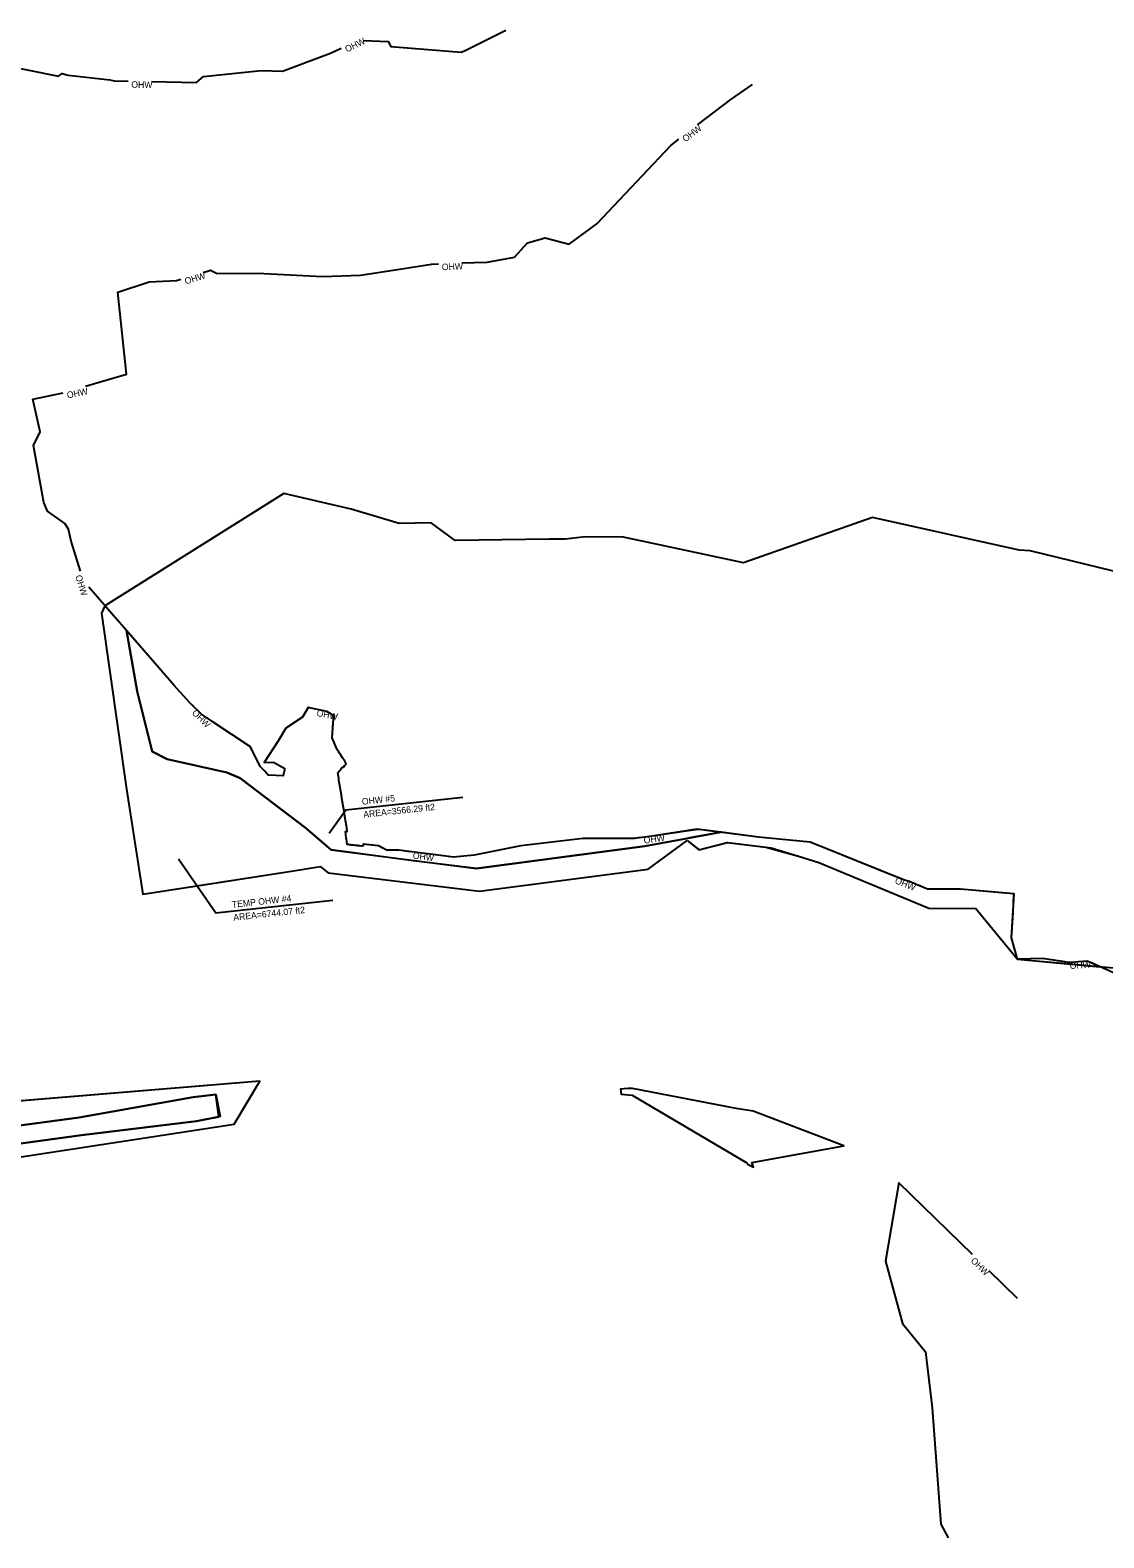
# Model space of a CAD drawing. Extents: x 1509537 to 1510685, y 401169 to 402194.
# Drawn here: x 1509933 to 1510396, y 401323 to 401974 of the extents above; entities that cross this region are included whole.
import ezdxf

# ---------------------------------------------------------------- set-up
doc = ezdxf.new("R2010")
doc.units = 0
for name, color, linetype in [('LAWE', 7, 'Continuous'), ('LAWE_P', 7, 'Continuous'), ('LAWE_P_T', 7, 'Continuous'), ('Level 6', 7, 'Continuous'), ('Level 9', 7, 'Continuous')]:
    doc.layers.add(name, color=color, linetype=linetype)

msp = doc.modelspace()

# ---------------------------------------------------------------- linework, layer by layer
at = {"layer": 'LAWE'}
for points in [[(1510076.76, 401969.93), (1510087.46, 401969.45), (1510088.64, 401967.38), (1510118.91, 401964.87), (1510120.62, 401965.57), (1510138.21, 401974.37)], [(1509902.92, 401964.05), (1509908.24, 401960.7), (1509910.79, 401962.61), (1509914.24, 401961.76), (1509918.65, 401959.85), (1509945.07, 401954.56), (1509946.65, 401955.7), (1509949.25, 401954.95), (1509967.25, 401952.86), (1509969.07, 401952.46), (1509975.16, 401952.34)], [(1509985.27, 401952.15), (1510004.66, 401951.79), (1510007.69, 401954.34), (1510032.6, 401956.88), (1510041.78, 401956.59), (1510058.69, 401963.04), (1510062.56, 401964.38), (1510067.12, 401966.6)], [(1510221.04, 401933.44), (1510235.42, 401944.42), (1510244.75, 401950.84)], [(1510119.27, 401873.82), (1510130.15, 401874.24), (1510141.95, 401876.27), (1510147.57, 401882.57), (1510155.29, 401884.73), (1510165.62, 401881.98), (1510177.56, 401890.72), (1510209.43, 401924.57), (1510213, 401927.3)], [(1510007.6, 401869.74), (1510010.77, 401870.69), (1510013.58, 401869.33), (1510030.98, 401869.37), (1510059.15, 401867.99), (1510075.43, 401868.58), (1510093.32, 401871.33), (1510106.13, 401873.32), (1510109.16, 401873.43)], [(1509956.82, 401820.56), (1509974.51, 401825.83), (1509970.69, 401861.22), (1509984.22, 401865.68), (1509996.1, 401866.3), (1509997.91, 401866.84)], [(1509954.57, 401740.76), (1509950.55, 401753.73), (1509949.47, 401758.83), (1509947.79, 401761.37), (1509940.39, 401766.71), (1509938.72, 401770.41), (1509934.35, 401794.94), (1509937.12, 401800.86), (1509934.08, 401815.08), (1509947.07, 401817.78)], [(1510003.48, 401682.27), (1510001.98, 401683.76), (1509994.99, 401691.34), (1509958.21, 401733.78)], [(1510055.56, 401681.27), (1510052.94, 401681.8), (1510050.48, 401677.68), (1510043.26, 401672.95), (1510040.12, 401667.55), (1510033.9, 401658.14), (1510037.93, 401658.25), (1510042.78, 401655.47), (1510042.73, 401655.24), (1510042.68, 401655.01), (1510042.63, 401654.78), (1510042.58, 401654.56), (1510042.53, 401654.34), (1510042.48, 401654.13), (1510042.43, 401653.92), (1510042.39, 401653.72), (1510042.34, 401653.51), (1510042.3, 401653.31), (1510042.26, 401653.12), (1510042.21, 401652.92), (1510042.17, 401652.73), (1510042.13, 401652.55), (1510042.09, 401652.36), (1510035.69, 401652.64), (1510034.15, 401654.4), (1510032.2, 401656.41), (1510028.02, 401664.83), (1510011.38, 401675.87)], [(1510096.9, 401619.58), (1510092.01, 401620.2), (1510086.88, 401620.26), (1510086.76, 401620.32), (1510086.63, 401620.39), (1510086.46, 401620.48), (1510086.26, 401620.59), (1510085.99, 401620.73), (1510085.64, 401620.91), (1510085.15, 401621.17), (1510084.41, 401621.56), (1510083.31, 401622.14), (1510083.21, 401622.15), (1510083.2, 401622.15), (1510081.95, 401622.28), (1510081.91, 401622.28), (1510081.86, 401622.29), (1510080.66, 401622.41), (1510080.58, 401622.42), (1510080.51, 401622.43), (1510079.35, 401622.54), (1510079.24, 401622.56), (1510079.14, 401622.57), (1510078.01, 401622.68), (1510077.88, 401622.7), (1510076.82, 401622.8), (1510076.66, 401622.82), (1510076.65, 401622.81), (1510076.61, 401622.59), (1510076.58, 401622.09), (1510076, 401622.02), (1510075.77, 401622.04), (1510075.14, 401622.11), (1510074.91, 401622.13), (1510074.28, 401622.19), (1510074.05, 401622.21), (1510073.42, 401622.28), (1510073.2, 401622.3), (1510072.56, 401622.36), (1510072.34, 401622.38), (1510072.12, 401622.4), (1510071.48, 401622.47), (1510071.27, 401622.49), (1510070.62, 401622.56), (1510070.28, 401622.64), (1510070.05, 401622.66), (1510069.76, 401622.64), (1510069.61, 401623.73), (1510069.57, 401624.05), (1510069.41, 401625.16), (1510069.37, 401625.45), (1510069.34, 401625.75), (1510069.18, 401626.86), (1510069.14, 401627.15), (1510068.98, 401628.28), (1510069.7, 401628.28), (1510069.81, 401628.3), (1510069.79, 401628.44), (1510069.69, 401629.08), (1510069.66, 401629.22), (1510069.56, 401629.87), (1510069.54, 401630.01), (1510069.43, 401630.66), (1510069.41, 401630.8), (1510069.3, 401631.45), (1510069.28, 401631.59), (1510069.17, 401632.24), (1510069.15, 401632.38), (1510069.04, 401633.03), (1510069.02, 401633.16), (1510068.92, 401633.82), (1510068.89, 401633.95), (1510068.79, 401634.6), (1510068.77, 401634.74), (1510068.66, 401635.39), (1510068.64, 401635.53), (1510068.53, 401636.18), (1510068.51, 401636.31), (1510068.4, 401636.97), (1510068.38, 401637.1), (1510068.27, 401637.76), (1510068.25, 401637.89), (1510068.14, 401638.55), (1510068.12, 401638.68), (1510068.02, 401639.34), (1510068, 401639.46), (1510067.89, 401640.13), (1510067.87, 401640.25), (1510067.76, 401640.92), (1510067.74, 401641.04), (1510067.63, 401641.7), (1510067.61, 401641.83), (1510067.5, 401642.49), (1510067.48, 401642.62), (1510067.37, 401643.28), (1510067.35, 401643.4), (1510067.24, 401644.07), (1510067.22, 401644.19), (1510067.11, 401644.86), (1510067.1, 401644.98), (1510066.99, 401645.65), (1510066.97, 401645.77), (1510066.86, 401646.44), (1510066.84, 401646.55), (1510066.73, 401647.23), (1510066.71, 401647.34), (1510066.6, 401648.02), (1510066.58, 401648.13), (1510066.47, 401648.81), (1510066.45, 401648.92), (1510066.34, 401649.6), (1510066.32, 401649.71), (1510066.21, 401650.39), (1510066.19, 401650.49), (1510066.08, 401651.17), (1510066.07, 401651.28), (1510065.95, 401651.96), (1510065.94, 401652.07), (1510065.83, 401652.75), (1510065.81, 401652.86), (1510065.7, 401653.54), (1510065.77, 401653.63), (1510066.2, 401654.2), (1510066.64, 401654.77), (1510066.7, 401654.85), (1510067.14, 401655.43), (1510067.2, 401655.5), (1510067.64, 401656.09), (1510067.69, 401656.15), (1510068.19, 401656.13), (1510068.2, 401656.14), (1510068.65, 401656.78), (1510068.67, 401656.81), (1510069.12, 401657.44), (1510069.33, 401657.74), (1510069.23, 401657.75), (1510068.67, 401658.74), (1510067.72, 401660.19), (1510066.99, 401661.3), (1510066.41, 401662.18), (1510065.94, 401662.9), (1510065.55, 401663.5), (1510065.23, 401664), (1510063.22, 401668.81), (1510063.71, 401675.33)], [(1510196.22, 401625.67), (1510193.84, 401625.35), (1510171.64, 401625.35), (1510144.69, 401622.16), (1510124.62, 401618.16), (1510115.63, 401617.22), (1510106.94, 401618.31)], [(1510305.71, 401609.17), (1510269.68, 401623.67), (1510247.29, 401625.93), (1510221.52, 401629.24), (1510221.18, 401629.22), (1510206.24, 401627.05)], [(1510380.23, 401571.92), (1510369.92, 401573.45), (1510359.21, 401573.2), (1510356.62, 401582.33), (1510357.76, 401601.44), (1510334.6, 401603.38), (1510320.34, 401603.35), (1510315.19, 401605.62)], [(1510469.91, 401515.23), (1510455.45, 401531.4), (1510452.85, 401535.8), (1510446.06, 401542.82), (1510435.1, 401552.57), (1510428.89, 401556.67), (1510422.58, 401559.27), (1510414.79, 401560.98), (1510390.37, 401571.86)], [(1510339.71, 401445.63), (1510308.01, 401476.56), (1510302.17, 401442.72), (1510309.51, 401415.81), (1510319.45, 401403.6), (1510322.38, 401379.43), (1510326.1, 401329.14), (1510329.27, 401323.28)], [(1510359.24, 401426.58), (1510346.96, 401438.57)]]:
    msp.add_lwpolyline(points, dxfattribs=at)
msp.add_lwpolyline([(1510244.53, 401485.4), (1510284.22, 401492.51), (1510245.03, 401507.57), (1510237.77, 401508.71), (1510192.97, 401517.27), (1510192.04, 401517.32), (1510190.95, 401517.35), (1510187.78, 401517.01), (1510188.1, 401514.91), (1510192.76, 401514.48), (1510242.3, 401485.2), (1510242.65, 401484.66), (1510245.14, 401483.41)], close=True, dxfattribs=at)
at = {"layer": 'LAWE_P'}
for points in [[(1510068.4, 401636.97), (1510068.38, 401637.1), (1510068.27, 401637.76), (1510068.25, 401637.89), (1510068.14, 401638.55), (1510068.12, 401638.68), (1510068.02, 401639.34), (1510068, 401639.46), (1510067.89, 401640.13), (1510067.87, 401640.25), (1510067.76, 401640.92), (1510067.74, 401641.04), (1510067.63, 401641.7), (1510067.61, 401641.83), (1510067.5, 401642.49), (1510067.48, 401642.62), (1510067.37, 401643.28), (1510067.35, 401643.4), (1510067.24, 401644.07), (1510067.22, 401644.19), (1510067.11, 401644.86), (1510067.1, 401644.98), (1510066.99, 401645.65), (1510066.97, 401645.77), (1510066.86, 401646.44), (1510066.84, 401646.55), (1510066.73, 401647.23), (1510066.71, 401647.34), (1510066.6, 401648.02), (1510066.58, 401648.13), (1510066.47, 401648.81), (1510066.45, 401648.92), (1510066.34, 401649.6), (1510066.32, 401649.71), (1510066.21, 401650.39), (1510066.19, 401650.49), (1510066.08, 401651.17), (1510066.07, 401651.28), (1510065.95, 401651.96), (1510065.94, 401652.07), (1510065.83, 401652.75), (1510065.81, 401652.86), (1510065.7, 401653.54), (1510065.77, 401653.63), (1510066.2, 401654.2), (1510066.64, 401654.77), (1510066.7, 401654.85), (1510067.14, 401655.43), (1510067.2, 401655.5), (1510067.64, 401656.09), (1510067.69, 401656.15), (1510068.19, 401656.13), (1510068.2, 401656.14), (1510068.65, 401656.78), (1510068.67, 401656.81), (1510069.12, 401657.44), (1510069.33, 401657.74), (1510069.23, 401657.75), (1510068.67, 401658.74), (1510067.72, 401660.19), (1510066.99, 401661.3), (1510066.41, 401662.18), (1510065.94, 401662.9), (1510065.55, 401663.5), (1510065.23, 401664), (1510063.22, 401668.81), (1510063.85, 401677.12), (1510063.68, 401677.7), (1510064.24, 401678.15), (1510060.92, 401680.18), (1510052.94, 401681.8), (1510050.48, 401677.68), (1510043.26, 401672.95), (1510040.12, 401667.55), (1510033.9, 401658.14), (1510037.93, 401658.25), (1510042.78, 401655.47), (1510042.73, 401655.24), (1510042.68, 401655.01), (1510042.63, 401654.78), (1510042.58, 401654.56), (1510042.53, 401654.34), (1510042.48, 401654.13), (1510042.43, 401653.92), (1510042.39, 401653.72), (1510042.34, 401653.51), (1510042.3, 401653.31), (1510042.26, 401653.12), (1510042.21, 401652.92), (1510042.17, 401652.73), (1510042.13, 401652.55), (1510042.09, 401652.36), (1510035.69, 401652.64), (1510034.15, 401654.4), (1510032.2, 401656.41), (1510028.02, 401664.83), (1510006.96, 401678.8), (1510001.98, 401683.76), (1509994.99, 401691.34), (1509974.4, 401715.1)], [(1509974.4, 401715.1), (1509979, 401688.94), (1509985.55, 401662.88), (1509991.95, 401659.58), (1510017.73, 401653.74), (1510023.58, 401651.34), (1510051.8, 401629.9), (1510062.8, 401620.41), (1510125.65, 401612.39), (1510198.34, 401621.95), (1510231.08, 401628.01), (1510220.76, 401629.34), (1510202.27, 401626.48)], [(1510202.27, 401626.48), (1510201.37, 401626.35), (1510193.84, 401625.35), (1510171.64, 401625.35), (1510144.69, 401622.16), (1510124.62, 401618.16), (1510115.63, 401617.22), (1510092.01, 401620.2), (1510086.88, 401620.26), (1510086.76, 401620.32), (1510086.63, 401620.39), (1510086.46, 401620.48), (1510086.26, 401620.59), (1510085.99, 401620.73), (1510085.64, 401620.91), (1510085.15, 401621.17), (1510084.41, 401621.56), (1510083.31, 401622.14), (1510083.21, 401622.15), (1510083.2, 401622.15), (1510081.95, 401622.28), (1510081.91, 401622.28), (1510081.86, 401622.29), (1510080.66, 401622.41), (1510080.58, 401622.42), (1510080.51, 401622.43), (1510079.35, 401622.54), (1510079.24, 401622.56), (1510079.14, 401622.57), (1510078.01, 401622.68), (1510077.88, 401622.7), (1510076.82, 401622.8), (1510076.66, 401622.82), (1510076.65, 401622.81), (1510076.61, 401622.59), (1510076.58, 401622.09), (1510076, 401622.02), (1510075.77, 401622.04), (1510075.14, 401622.11), (1510074.91, 401622.13), (1510074.28, 401622.19), (1510074.05, 401622.21), (1510073.42, 401622.28), (1510073.2, 401622.3), (1510072.56, 401622.36), (1510072.34, 401622.38), (1510072.12, 401622.4), (1510071.48, 401622.47), (1510071.27, 401622.49), (1510070.62, 401622.56), (1510070.28, 401622.64), (1510070.05, 401622.66), (1510069.76, 401622.64), (1510069.61, 401623.73), (1510069.57, 401624.05), (1510069.41, 401625.16), (1510069.37, 401625.45), (1510069.34, 401625.75), (1510069.18, 401626.86), (1510069.14, 401627.15), (1510068.98, 401628.28), (1510069.7, 401628.28), (1510069.81, 401628.3), (1510069.79, 401628.44), (1510069.69, 401629.08), (1510069.66, 401629.22), (1510069.56, 401629.87), (1510069.54, 401630.01), (1510069.43, 401630.66), (1510069.41, 401630.8), (1510069.3, 401631.45), (1510069.28, 401631.59), (1510069.17, 401632.24), (1510069.15, 401632.38), (1510069.04, 401633.03), (1510069.02, 401633.16), (1510068.92, 401633.82), (1510068.89, 401633.95), (1510068.79, 401634.6), (1510068.77, 401634.74), (1510068.66, 401635.39), (1510068.64, 401635.53), (1510068.53, 401636.18), (1510068.51, 401636.31), (1510068.45, 401636.7), (1510068.4, 401636.97)], [(1509905.49, 401490.46), (1509955.04, 401497.19), (1510004.67, 401503.29), (1510014.27, 401505.12), (1510012.96, 401514.79), (1510003.27, 401513.6), (1509954, 401504.87), (1509904.45, 401498.18)]]:
    msp.add_lwpolyline(points, dxfattribs=at)
at = {"layer": 'LAWE_P_T'}
for points in [[(1510062, 401627.65), (1510069.1, 401637.62), (1510119.7, 401643.14)], [(1509996.97, 401616.45), (1510012.98, 401593.14), (1510063.57, 401598.65)]]:
    msp.add_lwpolyline(points, dxfattribs=at)
at = {"layer": 'Level 6'}
for p, q in [((1509974.4, 401715.1), (1509965.11, 401725.82)), ((1510023.58, 401651.34), (1510017.73, 401653.74)), ((1510051.8, 401629.9), (1510023.58, 401651.34)), ((1510046.59, 401611.34), (1510058.01, 401613.13)), ((1510394.73, 401569.92), (1510393.44, 401570.5))]:
    msp.add_line(p, q, dxfattribs=at)
for points in [[(1509965.11, 401725.82), (1509963.64, 401722.59), (1509974.39, 401646.63)], [(1509985.55, 401662.88), (1509979, 401688.94), (1509974.4, 401715.1)], [(1510017.73, 401653.74), (1509991.95, 401659.58), (1509985.55, 401662.88)], [(1509974.39, 401646.63), (1509981.47, 401601.19), (1510004.94, 401604.85), (1510046.59, 401611.34)], [(1510215.62, 401625.15), (1510198.34, 401621.95), (1510125.65, 401612.39), (1510098.28, 401615.69), (1510062.8, 401620.41), (1510051.8, 401629.9)], [(1510352.36, 401601.89), (1510334.6, 401603.38), (1510320.34, 401603.35), (1510312.58, 401606.77), (1510310.39, 401607.29), (1510269.68, 401623.67), (1510247.29, 401625.93), (1510231.28, 401628.04), (1510219.15, 401625.8), (1510215.62, 401625.15)], [(1510058.01, 401613.13), (1510061.48, 401610.5), (1510126.95, 401602.48), (1510199.65, 401612.04), (1510216.62, 401624.36)], [(1510216.62, 401624.36), (1510221.68, 401620.37), (1510221.68, 401620.37), (1510234.15, 401623.58), (1510250.52, 401621.58), (1510264.69, 401617.6)], [(1510264.69, 401617.6), (1510273.34, 401614.89), (1510320.84, 401595.24), (1510341.25, 401595.13), (1510359.21, 401573.2), (1510394.73, 401569.92)], [(1510357.28, 401593.4), (1510357.59, 401601.45), (1510352.36, 401601.89)], [(1510382.76, 401571.79), (1510381.64, 401571.71), (1510369.92, 401573.45), (1510359.21, 401573.2), (1510356.62, 401582.33), (1510357.28, 401593.4)], [(1510393.44, 401570.5), (1510389.3, 401572.34), (1510385.37, 401571.96), (1510382.76, 401571.79)], [(1509856.53, 401476.73), (1510020.93, 401501.99), (1510032.06, 401520.51), (1509918.51, 401511.14)], [(1509904.45, 401498.18), (1509954, 401504.87), (1510003.27, 401513.6), (1510012.96, 401514.79), (1510014.93, 401505.24), (1510004.67, 401503.29), (1509955.04, 401497.19), (1509905.49, 401490.46)]]:
    msp.add_lwpolyline(points, dxfattribs=at)
at = {"layer": 'Level 9'}
for points in [[(1510071.47, 401767.53), (1510042.45, 401774.24), (1509965.11, 401725.82)], [(1510436.07, 401732.12), (1510364.69, 401749.47), (1510359.87, 401749.85), (1510296.54, 401763.85), (1510240.81, 401744.39), (1510188.36, 401755.57), (1510171.41, 401755.43), (1510164.04, 401754.57), (1510157.01, 401754.5), (1510136.7, 401754.21), (1510116.39, 401753.93), (1510106.06, 401761.59), (1510092.26, 401761.29), (1510071.47, 401767.53)], [(1509965.11, 401725.82), (1509963.64, 401722.59), (1509974.39, 401646.63)], [(1509974.39, 401646.63), (1509974.39, 401646.63), (1509981.47, 401601.19), (1510046.59, 401611.34), (1510058.01, 401613.13)], [(1510058.01, 401613.13), (1510061.48, 401610.5), (1510126.95, 401602.48), (1510199.65, 401612.04), (1510216.62, 401624.36)], [(1510216.62, 401624.36), (1510221.56, 401620.42), (1510233.84, 401623.61), (1510252.89, 401621.29), (1510264.69, 401617.6)], [(1510264.69, 401617.6), (1510273.34, 401614.89), (1510320.84, 401595.24), (1510341.25, 401595.13), (1510359.26, 401573.21), (1510402.23, 401569.23), (1510422.39, 401569.68), (1510423.42, 401580.07), (1510422.96, 401609.85), (1510436.45, 401620.31), (1510452.26, 401619.93), (1510463.51, 401615.28), (1510484.53, 401619.58)], [(1509767.58, 401349.35), (1509773.28, 401363.45), (1509774.1, 401368.36), (1509778.17, 401371.6), (1509783.48, 401379.52), (1509796.56, 401386.39), (1509806.06, 401398.55), (1509809.1, 401403.54), (1509809.07, 401412), (1509856.53, 401476.73), (1510020.93, 401501.99), (1510032.06, 401520.51), (1509866.77, 401506.88)]]:
    msp.add_lwpolyline(points, dxfattribs=at)

# ---------------------------------------------------------------- texts
at = {"layer": 'LAWE'}
for rotation, p in [(25.89056, (1510069.61, 401964.69)), (358.92366, (1509976.5, 401949.52)), (37.37913, (1510215.82, 401925.92)), (2.20264, (1510110.67, 401870.69)), (16.65374, (1510000.05, 401864.56)), (11.71895, (1509949.01, 401815.32)), (287.25387, (1509952.31, 401738.59)), (315.06614, (1510002.49, 401679.3)), (348.5179, (1510056.37, 401678.25)), (7.52511, (1510197.97, 401623.07)), (352.81491, (1510097.94, 401616.63)), (338.08205, (1510305.97, 401606.05)), (3.79285, (1510381.83, 401568.92)), (315.70831, (1510338.76, 401442.65))]:
    msp.add_text('OHW', height=2.8, rotation=rotation, dxfattribs=at).set_placement(p)
at = {"layer": 'LAWE_P_T'}
for s, p in [('OHW #5', (1510076.23, 401639.81)), ('AREA=3566.29 ft2', (1510076.84, 401634.24)), ('TEMP OHW #4', (1510020.11, 401595.32)), ('AREA=6744.07 ft2', (1510020.71, 401589.76))]:
    msp.add_text(s, height=2.8, rotation=6.2219, dxfattribs=at).set_placement(p)

doc.saveas('drawing.dxf')
